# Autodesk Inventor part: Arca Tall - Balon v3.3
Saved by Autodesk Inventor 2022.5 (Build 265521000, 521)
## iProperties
Created: 2024-07
Part Number: Arca Tall - Balon v3.3
Material: Generic
Document SubType Name: Modeling
Designer: AdminForWorker
Density: 1 g/cm^3
Appearance: Default
Title: Arca Tall - Balon v3.3
Author: AdminForWorker
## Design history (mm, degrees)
feature "Balon v3.3"
body "Solid1"
